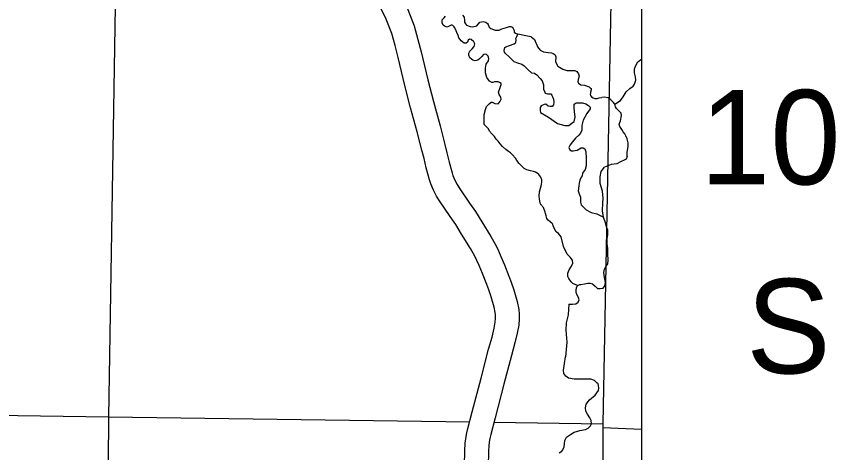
# Model space of a CAD drawing. Extents: x 8749 to 11879, y 13275 to 15339.
# Drawn here: x 10827.5 to 11000.8, y 13636.9 to 13729.3 of the extents above; entities that cross this region are included whole.
import ezdxf

# ---------------------------------------------------------------- set-up
doc = ezdxf.new("R2010")
doc.units = 0
for name, color, linetype in [('Level 10', 7, 'Continuous'), ('Level 35', 7, 'Continuous'), ('Level 4', 7, 'Continuous'), ('Level 5', 7, 'Continuous'), ('R_Draft', 7, 'Continuous')]:
    doc.layers.add(name, color=color, linetype=linetype)

msp = doc.modelspace()

# ---------------------------------------------------------------- linework, layer by layer
at = {"layer": 'Level 10'}
for points in [[(10908.25, 13720.55), (10907.59, 13723.1), (10906.9, 13725.65), (10905.69, 13728.7), (10903.5, 13733.26), (10900.64, 13739.36), (10899.65, 13741.3), (10899.04, 13742.7), (10898.32, 13744.72), (10897.88, 13746.44), (10897.65, 13747.6), (10897.61, 13748.35), (10897.67, 13751.9), (10897.71, 13758.83)], [(10902.71, 13758.8), (10902.67, 13751.85), (10902.62, 13748.44), (10902.63, 13748.22), (10902.76, 13747.55), (10903.11, 13746.18), (10903.69, 13744.54), (10904.18, 13743.43), (10905.13, 13741.56), (10908.01, 13735.4), (10910.27, 13730.71), (10911.66, 13727.23), (10912.42, 13724.37), (10913.1, 13721.75)], [(10913.1, 13721.75), (10914.49, 13715.86), (10915.71, 13711.22), (10917.13, 13706.11), (10918.1, 13702.16), (10918.57, 13700.34), (10919.01, 13698.39), (10919.63, 13696.11), (10919.81, 13695.56), (10920.24, 13694.57), (10920.69, 13693.67), (10921.13, 13693), (10923.34, 13689.75), (10924.6, 13687.96), (10925.93, 13685.8), (10927.86, 13682.63)], [(10923.55, 13680.1), (10921.66, 13683.19), (10920.42, 13685.21), (10919.23, 13686.9), (10916.96, 13690.24), (10916.35, 13691.18), (10915.7, 13692.45), (10915.13, 13693.79), (10914.85, 13694.66), (10914.16, 13697.18), (10913.71, 13699.16), (10913.25, 13700.94), (10912.29, 13704.84), (10910.88, 13709.92), (10909.64, 13714.65), (10908.25, 13720.55)], [(10927.86, 13682.63), (10928.96, 13680.7), (10929.46, 13679.64), (10929.98, 13678.46), (10930.7, 13676.7), (10931.68, 13674.3), (10932.15, 13673), (10932.7, 13671.38), (10933.43, 13668.88), (10933.74, 13667.21), (10933.81, 13666.25), (10933.81, 13665.24), (10933.74, 13663.92), (10933.42, 13662.22), (10932.95, 13660.16), (10932.21, 13657.48), (10930.62, 13651.38), (10928.74, 13644.28), (10927.85, 13640.75), (10927.63, 13639.93), (10927.54, 13639.52), (10927.43, 13638.52), (10927.36, 13637.08), (10927.28, 13634.07)], [(10922.28, 13634.17), (10922.36, 13637.27), (10922.44, 13638.92), (10922.6, 13640.32), (10922.77, 13641.11), (10923.01, 13642.02), (10923.9, 13645.53), (10925.78, 13652.65), (10927.38, 13658.78), (10928.1, 13661.38), (10928.52, 13663.24), (10928.77, 13664.52), (10928.81, 13665.36), (10928.81, 13666.07), (10928.77, 13666.58), (10928.56, 13667.73), (10927.93, 13669.88), (10927.43, 13671.35), (10927.02, 13672.5), (10926.07, 13674.81), (10925.38, 13676.5), (10924.91, 13677.57), (10924.52, 13678.39), (10923.55, 13680.1)]]:
    msp.add_lwpolyline(points, dxfattribs=at)
at = {"layer": 'Level 35'}
for points in [[(10920.65, 13725.85), (10920.4, 13726.54), (10920.2, 13726.82), (10920.07, 13727.05), (10919.79, 13727.35), (10919.69, 13727.43), (10919.44, 13727.4), (10919.04, 13727.18), (10918.58, 13727), (10918.15, 13727.1), (10917.77, 13727.43), (10917.55, 13727.91), (10917.55, 13728.52), (10917.95, 13728.97), (10918.25, 13729.27)], [(10921.86, 13729.5), (10922.19, 13729.1), (10922.27, 13728.39), (10922.29, 13728.01), (10922.5, 13727.66), (10922.7, 13727.43), (10923.48, 13727.13), (10923.97, 13727.08)], [(10923.97, 13727.08), (10924.87, 13727.28), (10925.5, 13728.04), (10926.23, 13728.19), (10926.79, 13728.06), (10927.17, 13727.78), (10927.3, 13727.51)], [(10927.55, 13715.53), (10926.97, 13716.34), (10926.71, 13717.28), (10926.74, 13718.31), (10926.87, 13719.17), (10927.32, 13719.85), (10927.42, 13720.36), (10927.3, 13720.84), (10926.92, 13721.19), (10926.64, 13721.27), (10926.26, 13721.17), (10925.91, 13720.76), (10925.43, 13720.26), (10925.07, 13720.01), (10924.52, 13719.85), (10924.06, 13719.96), (10923.43, 13720.51), (10923.18, 13721.04), (10923.18, 13721.47), (10923.38, 13721.93), (10923.86, 13722.38), (10924.29, 13722.86), (10924.44, 13723.42), (10924.24, 13723.9), (10923.68, 13724.38), (10923.36, 13724.43), (10923.03, 13724.2), (10922.9, 13723.8), (10922.65, 13723.57), (10922.17, 13723.57), (10921.54, 13724.1), (10921.08, 13724.71), (10920.96, 13725.21), (10920.65, 13725.85)], [(10927.3, 13727.51), (10927.47, 13726.97), (10927.85, 13726.67), (10928.76, 13726.37), (10929.22, 13726.34), (10929.57, 13726.37), (10930.2, 13726.59), (10931.16, 13726.92), (10931.77, 13727.15), (10932.07, 13727.13), (10932.32, 13726.95), (10932.57, 13726.7), (10932.78, 13726.24), (10932.8, 13725.94), (10933.03, 13725.71), (10933.58, 13725.47)], [(10931.71, 13720.73), (10930.91, 13721.42), (10930.73, 13721.67), (10930.68, 13722.05), (10930.71, 13722.36), (10930.83, 13722.69), (10931.03, 13722.81), (10931.79, 13723.09), (10932.75, 13723.42), (10933.1, 13723.72), (10933.18, 13724.2), (10933.16, 13724.61), (10933.31, 13725.01), (10933.58, 13725.47)], [(10936.38, 13724.91), (10935.23, 13725.11), (10933.58, 13725.47)], [(10936.38, 13724.91), (10937.09, 13724.38), (10937.39, 13723.67), (10937.49, 13723.37), (10937.74, 13722.84), (10938.25, 13722.1), (10938.98, 13721.73), (10939.46, 13721.65), (10939.97, 13721.62), (10940.67, 13721.55), (10941, 13721.37), (10941.46, 13721.12), (10941.61, 13720.69), (10941.53, 13719.65), (10942.04, 13718.74), (10943.05, 13718.06), (10943.91, 13717.78), (10944.46, 13717.78)], [(10931.71, 13720.73), (10932.34, 13720.05), (10932.73, 13719.73), (10933.46, 13719.44), (10934.39, 13719.11), (10934.87, 13718.76), (10935.75, 13717.97), (10936.46, 13717.34), (10937.07, 13717.24), (10937.57, 13716.89), (10938.26, 13716.1), (10938.71, 13715.6), (10938.96, 13714.79), (10938.99, 13713.83), (10939.27, 13713.25), (10939.34, 13713.04), (10939.85, 13712.87), (10940.3, 13712.89), (10940.5, 13712.87), (10940.76, 13712.56), (10941.06, 13711.75), (10941.16, 13711.12), (10941.13, 13710.57), (10940.83, 13710.21), (10940.4, 13710.16), (10939.97, 13710.26), (10939.44, 13710.67), (10939.11, 13710.64), (10938.51, 13710.34), (10938.26, 13709.98), (10938.26, 13709.33), (10938.33, 13708.9), (10940.02, 13707.89), (10941.92, 13706.6), (10943.48, 13706.14), (10944.32, 13706.19), (10944.97, 13706.67), (10945.48, 13707.03), (10945.68, 13707.96), (10945.53, 13709.12), (10945.48, 13709.91), (10945.48, 13710.34), (10945.5, 13710.67), (10945.86, 13710.94), (10946.03, 13710.97)], [(10954.09, 13710.67), (10955.24, 13711.47), (10955.8, 13712.23), (10956.46, 13713.27), (10957.26, 13714), (10957.97, 13714.46), (10958.22, 13714.88), (10958.53, 13715.74), (10958.43, 13716.48), (10958.2, 13717.29), (10958.25, 13718.17), (10958.53, 13718.88), (10958.96, 13719.66), (10959.72, 13720.19)], [(10944.46, 13717.78), (10945.6, 13717.77), (10946.03, 13717.62), (10946.41, 13717.13), (10946.51, 13716.63), (10946.31, 13715.92), (10946.26, 13715.37), (10946.38, 13715.14), (10946.89, 13714.78), (10947.65, 13714.68), (10948.63, 13714.35), (10948.88, 13714.13), (10949.04, 13713.97), (10949.09, 13713.7), (10948.93, 13713.24), (10948.91, 13712.94), (10948.88, 13712.81), (10948.91, 13712.48), (10949.14, 13712.26), (10949.49, 13712), (10949.84, 13711.88), (10950.3, 13711.88), (10950.78, 13712), (10951.31, 13712.1)], [(10927.32, 13705.43), (10926.84, 13705.96), (10926.44, 13706.39), (10926.44, 13707.02), (10926.44, 13708.49), (10926.69, 13709.53), (10926.92, 13710.18), (10927.5, 13710.77), (10927.93, 13711.09), (10928.15, 13711.09), (10928.71, 13710.79), (10929.42, 13710.77), (10929.72, 13711.17), (10930, 13711.7), (10929.97, 13712.18), (10929.59, 13712.71), (10929.44, 13713.19), (10929.82, 13714.2), (10930.05, 13714.81), (10930, 13715.06), (10929.69, 13715.29), (10929.42, 13715.39), (10929.14, 13715.42), (10928.61, 13715.37), (10928.26, 13715.27), (10928.05, 13715.27), (10927.55, 13715.53)], [(10956.64, 13699.62), (10956.71, 13700.43), (10956.92, 13701.77), (10956.89, 13702.48), (10956.71, 13703.32), (10956.41, 13703.95), (10956.16, 13704.43), (10955.83, 13704.83), (10955.55, 13705.31), (10955.12, 13705.95), (10955, 13706.45), (10955.25, 13707.16), (10955.5, 13708.27), (10955.43, 13708.78), (10954.74, 13709.41), (10954.42, 13709.74), (10954.21, 13710.14), (10954.09, 13710.67), (10953.81, 13711.03), (10953.25, 13711.58), (10952.65, 13712.01), (10951.89, 13712.16), (10951.31, 13712.1)], [(10946.03, 13710.97), (10947.22, 13710.93), (10947.95, 13710.78), (10948.51, 13710.37), (10948.83, 13710.04), (10948.86, 13709.67), (10948.13, 13708.68), (10947.37, 13707.29), (10947.07, 13706.15), (10947.12, 13705.17), (10946.81, 13704.56), (10946.48, 13704.13), (10945.78, 13703.47), (10945.12, 13702.71), (10944.59, 13702.08), (10944.34, 13701.5), (10944.54, 13701.02), (10944.89, 13700.82), (10945.22, 13700.79), (10946.11, 13700.97), (10946.96, 13701.4), (10947.39, 13701.42), (10947.72, 13701.2), (10947.95, 13700.59), (10948, 13699.22), (10948.03, 13697.61), (10947.8, 13696.86)], [(10938.43, 13695.2), (10937.98, 13695.82), (10937.67, 13696.07), (10937.32, 13696.3), (10936.84, 13696.4), (10936.23, 13696.53), (10935.45, 13696.78), (10934.9, 13697.06), (10934.44, 13697.49), (10933.81, 13698.12), (10933.33, 13698.73), (10933.03, 13699.26), (10932.45, 13699.96), (10932.02, 13700.34), (10931.59, 13700.67), (10931.03, 13701.08), (10930.3, 13701.71), (10929.84, 13702.26), (10929.39, 13702.82), (10928.99, 13703.3), (10928.61, 13703.86), (10928.13, 13704.36), (10927.55, 13704.94), (10927.32, 13705.43)], [(10956.64, 13699.62), (10956.49, 13699.06), (10956.21, 13698.86), (10955.3, 13698.5), (10954.47, 13698.07), (10953.28, 13697.92), (10951.86, 13697.35)], [(10947.8, 13696.86), (10947.24, 13696.08), (10947.17, 13695.52), (10946.94, 13695.19), (10946.69, 13694.56), (10946.51, 13693.96), (10946.43, 13693.4), (10946.33, 13692.34), (10946.51, 13691.73), (10946.79, 13691), (10946.84, 13690.37), (10946.79, 13689.96), (10946.94, 13689.4), (10948.03, 13688.32), (10949.06, 13687.76), (10950.27, 13687.46), (10951.66, 13686.78)], [(10952.57, 13683.08), (10952.6, 13684), (10952.39, 13684.48), (10952.07, 13685.57), (10951.66, 13686.78), (10951.44, 13688.09), (10951.51, 13689.81), (10951.61, 13690.72), (10951.56, 13691.48), (10951.44, 13692.24), (10950.98, 13693.86), (10950.96, 13695.3), (10951.21, 13696.41), (10951.86, 13697.35)], [(10938.96, 13688.83), (10938.35, 13689.54), (10938.17, 13690.14), (10938.1, 13690.67), (10938.07, 13691.18), (10938.1, 13692.14), (10938.35, 13692.87), (10938.55, 13693.66), (10938.63, 13694.21), (10938.6, 13694.64), (10938.43, 13695.2)], [(10942.7, 13682.58), (10942.17, 13683.32), (10941.69, 13683.64), (10941.38, 13684.18), (10941.05, 13684.93), (10940.93, 13685.26), (10940.75, 13685.47), (10940.45, 13685.72), (10939.99, 13686.1), (10939.66, 13686.48), (10939.51, 13687.01), (10939.39, 13687.54), (10939.34, 13687.84), (10938.96, 13688.83)], [(10946.18, 13672.28), (10945.2, 13672.74), (10944.82, 13673.1), (10944.36, 13673.75), (10944.11, 13674.23), (10944.16, 13674.92), (10944.44, 13675.6), (10944.89, 13676.36), (10945.2, 13676.99), (10945.12, 13677.67), (10944.62, 13678.31), (10943.96, 13678.91), (10943.18, 13680.56), (10942.7, 13682.58)], [(10948.88, 13672.78), (10949.31, 13672.62), (10949.89, 13672.14), (10950.4, 13671.68), (10950.98, 13671.68), (10951.59, 13671.73), (10951.94, 13672.19), (10952.07, 13672.95), (10951.89, 13673.98), (10951.74, 13675.04), (10951.89, 13675.73), (10952.22, 13676.38), (10952.22, 13676.41), (10952.57, 13676.91), (10952.67, 13677.62), (10952.62, 13678.96), (10952.62, 13680.1), (10952.47, 13681.11), (10952.45, 13682.2), (10952.57, 13683.08)], [(10944.33, 13668.31), (10945.12, 13668.31), (10945.83, 13668.38), (10946.28, 13668.79), (10946.51, 13669.27), (10946.36, 13669.77), (10946.11, 13670.26), (10945.9, 13670.79), (10945.9, 13671.32), (10945.93, 13671.77), (10946.18, 13672.28), (10946.66, 13672.51), (10946.91, 13672.51), (10947.62, 13672.66), (10948.35, 13672.76), (10948.88, 13672.78)], [(10944.33, 13668.31), (10944.19, 13666.1), (10943.79, 13664.38), (10943.69, 13662.86), (10943.89, 13660.28), (10943.66, 13657.19)], [(10949.92, 13649.1), (10950.63, 13650.09), (10950.66, 13650.57), (10950.63, 13651.13), (10950.51, 13651.45), (10950.33, 13651.63), (10949.75, 13652.16), (10949.75, 13652.16), (10948.99, 13652.44), (10947.93, 13652.47), (10947.35, 13652.47), (10946.34, 13652.49), (10945.45, 13652.49), (10944.27, 13652.67), (10943.69, 13653.07), (10943.26, 13653.68), (10943.23, 13654.36), (10943.66, 13657.19)], [(10943.44, 13638.74), (10943.51, 13639.51), (10943.84, 13640.17), (10944.7, 13640.73), (10945.45, 13641.21), (10946.64, 13641.61), (10947.83, 13641.81), (10948.46, 13642.09), (10948.91, 13642.6), (10949.14, 13643), (10949.09, 13643.71), (10948.79, 13644.29), (10948.26, 13645.08), (10947.93, 13645.66), (10947.88, 13646.39), (10948, 13647.17), (10948.69, 13648.11), (10949.92, 13649.1)], [(10942.28, 13636.89), (10942.83, 13637.2), (10943.08, 13637.5), (10943.36, 13638.16), (10943.44, 13638.74)]]:
    msp.add_lwpolyline(points, dxfattribs=at)
at = {"layer": 'Level 4'}
msp.add_lwpolyline([(10953.53, 13820.42), (10953.48, 13747.58), (10953.48, 13747.19), (10951.54, 13643.03), (10951.54, 13642.23), (10951.1, 13546.98)], dxfattribs=at)
at = {"layer": 'Level 5'}
for points in [[(10848.7, 13748.87), (10846.99, 13644.47)], [(10798.9, 13645.2), (10846.99, 13644.47)], [(10846.99, 13644.47), (10846.23, 13538.28)], [(10846.99, 13644.47), (10923.37, 13643.41)], [(10928.51, 13643.34), (10951.54, 13643.03)], [(10951.54, 13642.23), (10959.72, 13641.87)]]:
    msp.add_lwpolyline(points, dxfattribs=at)
at = {"layer": 'R_Draft'}
msp.add_lwpolyline([(9678.09, 14456.3), (10959.72, 14456.3), (10959.72, 13439.87), (9678.09, 13439.87)], close=True, dxfattribs=at)

# ---------------------------------------------------------------- texts
for s, p in [('10', (10972.06, 13693.69)), ('S', (10981.87, 13653.69))]:
    msp.add_text(s, height=20, dxfattribs=at).set_placement(p)

doc.saveas('drawing.dxf')
